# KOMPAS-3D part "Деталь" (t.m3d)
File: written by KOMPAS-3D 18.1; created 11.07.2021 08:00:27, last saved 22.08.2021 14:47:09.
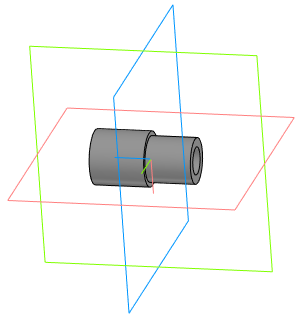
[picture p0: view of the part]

Document properties: Автор: 111; Полное имя файла: C:\Users\admin\Desktop\ffb\t.m3d

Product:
- Part/product: Деталь
    Масса: 0.0119453
    source file: 8.cdw

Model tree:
1. Эскиз:1
2. Элемент выдавливания:1
     Расстояние 1 = 12
3. Эскиз:2
4. Элемент выдавливания:2
     Расстояние 1 = -10
5. Эскиз:4  (with: Элемент выдавливания:2)
6. Элемент выдавливания:4
     Расстояние 2 = 30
